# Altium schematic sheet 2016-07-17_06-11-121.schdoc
size 241 x 111 mm; SheetNumber: 1; SheetTotal: 1
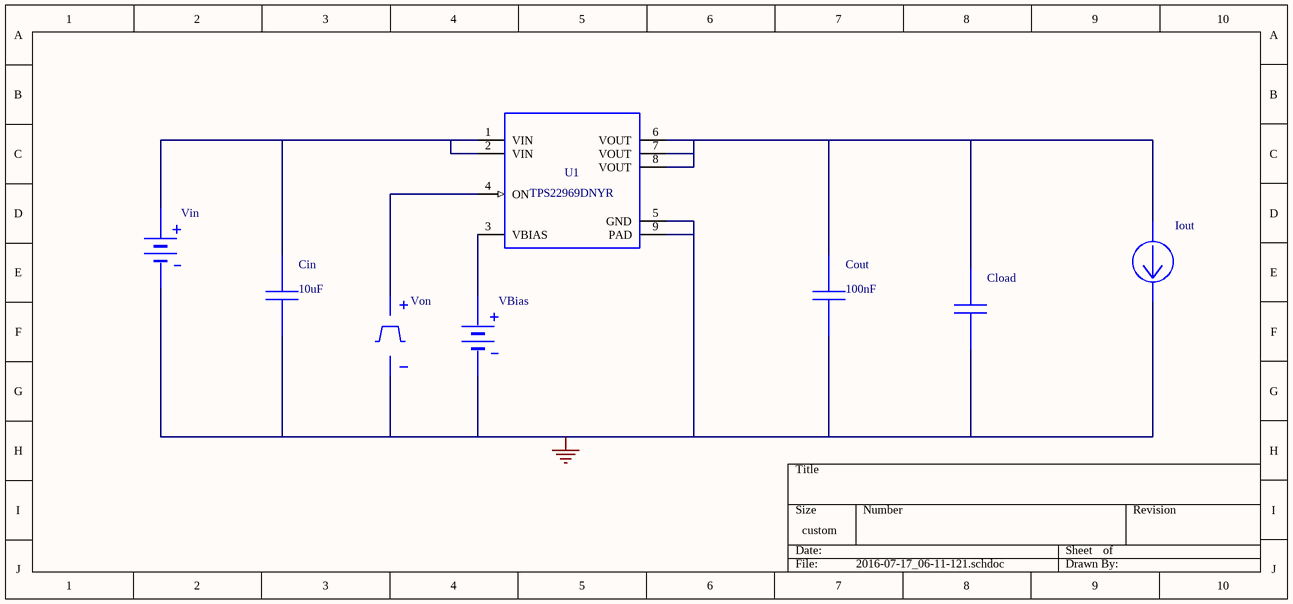
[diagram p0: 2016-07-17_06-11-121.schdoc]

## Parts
Cin  value 10uF  (hidden comment: GRM219R60J106KE19D)
Cload  GRM21BR71E104KA01L  (value not drawn)
Cout  value 100nF  (hidden comment: GRM155R60J104KA01D)
Iout  WB_CURRENT_LOAD  (value not drawn)
U1  TPS22969DNYR
VBias  WB_PRIM_DC_VOLTAGE_SOURCE  (value not drawn)
Vin  WB_BATTERY  (value not drawn)
Von  WB_PRIM_PWL_VOLTAGE_SOURCE  (value not drawn)

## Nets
0: Cin.2 Cload.2 Cout.2 Iout.2(-) U1.5(GND) U1.9(PAD) VBias.2(-) Vin.2(-) Von.2(-)
NetCin_1: Cin.1 U1.1(VIN) U1.2(VIN) Vin.1(+)
NetCload_1: Cload.1 Cout.1 Iout.1(+) U1.6(VOUT) U1.7(VOUT) U1.8(VOUT)
NetU1_3: U1.3(VBIAS) VBias.1(+)
NetU1_4: U1.4(ON) Von.1(+)

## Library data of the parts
Cin = GRM219R60J106KE19D: GRM219R60J106KE1; Manufacturer Name: MuRata
Cload = GRM21BR71E104KA01L: WB_PRIMITIVE_CAP; Manufacturer Name: WB_PRIMITIVE_CAPACITOR
Cout = GRM155R60J104KA01D: GRM155R60J104KA0; Manufacturer Name: MuRata
U1 = TPS22969DNYR: Manufacturer Name: Texas Instruments
VBias = WB_PRIM_DC_VOLTAGE_SOURCE: WB_PRIM_DC_VOLTA
Von = WB_PRIM_PWL_VOLTAGE_SOURCE: WB_PRIM_PWL_VOLT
